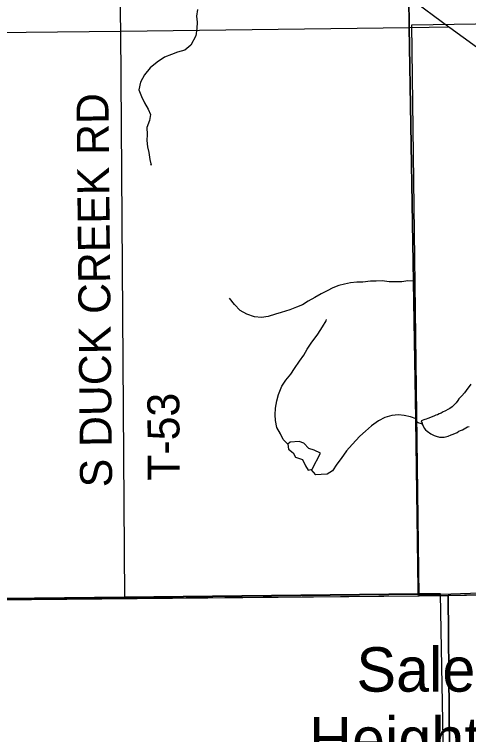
# Model space of a CAD drawing. Extents: x 0 to 34, y 0 to 22.
# Drawn here: x 2.754 to 3.561, y 16.976 to 18.256 of the extents above; entities that cross this region are included whole.
import ezdxf

# ---------------------------------------------------------------- set-up
doc = ezdxf.new("R2010")
doc.units = 0
for name, color, linetype in [('GM_X_County_Road', 7, 'Continuous'), ('GM_X_Minor_Lake', 7, 'Continuous'), ('GM_X_Minor_River', 7, 'Continuous'), ('GM_X_Rail_Line', 7, 'Continuous'), ('GM_X_Section', 7, 'Continuous'), ('GM_X_State_Route', 7, 'Continuous'), ('GM_X_Township', 7, 'Continuous'), ('GM_X_Township_Road', 7, 'Continuous'), ('GM_X_Township_Road_Text', 7, 'Continuous'), ('GM_X_Unincorporated_Text', 7, 'Continuous'), ('GM_X_US_Route', 7, 'Continuous'), ('SH_Cut_Line', 7, 'Continuous')]:
    doc.layers.add(name, color=color, linetype=linetype)

msp = doc.modelspace()

# ---------------------------------------------------------------- linework, layer by layer
at = {"layer": 'GM_X_County_Road'}
msp.add_lwpolyline([(2.1, 18.2179), (2.9425, 18.2267), (3.4555, 18.2333)], dxfattribs=at)
at = {"layer": 'GM_X_Minor_Lake'}
for points in [[(3.5646, 17.5993), (3.5564, 17.5878), (3.5534, 17.584), (3.5489, 17.5786), (3.5463, 17.5763)], [(3.5463, 17.5763), (3.5433, 17.5729), (3.5414, 17.5698), (3.5384, 17.566), (3.535, 17.5621), (3.5313, 17.5587), (3.5275, 17.5556), (3.5249, 17.5544), (3.5185, 17.5509), (3.5155, 17.5497), (3.5117, 17.5478), (3.5087, 17.5466), (3.5053, 17.5447), (3.5026, 17.5439), (3.4992, 17.5423), (3.4883, 17.538), (3.4856, 17.5372), (3.483, 17.5364), (3.4764, 17.5337)], [(3.4764, 17.5337), (3.4781, 17.5299), (3.4789, 17.5273), (3.482, 17.5212), (3.4843, 17.5182), (3.4874, 17.5156), (3.4939, 17.5107), (3.4996, 17.5077), (3.5031, 17.5066), (3.5092, 17.5052), (3.5118, 17.5048), (3.5175, 17.5049), (3.5243, 17.5069), (3.53, 17.5092), (3.5334, 17.5104), (3.5405, 17.5135), (3.5435, 17.5155), (3.5466, 17.517), (3.5496, 17.5182), (3.559, 17.5233), (3.5617, 17.5241)], [(3.2974, 17.4764), (3.2864, 17.482), (3.2769, 17.4846), (3.2681, 17.494), (3.2597, 17.4974), (3.2435, 17.4961), (3.2393, 17.4922), (3.2406, 17.4835), (3.249, 17.4768), (3.2532, 17.4696), (3.2653, 17.4651), (3.2711, 17.4538), (3.2754, 17.4462), (3.2825, 17.4482)], [(3.2825, 17.4482), (3.2974, 17.4764)]]:
    msp.add_lwpolyline(points, dxfattribs=at)
at = {"layer": 'GM_X_Minor_River'}
for points in [[(3.0789, 18.2654), (3.0771, 18.2536), (3.0784, 18.2426), (3.0777, 18.2312), (3.0759, 18.2183), (3.067, 18.2015), (3.0565, 18.1931), (3.0433, 18.1892), (3.0327, 18.1849), (3.0206, 18.1806), (3.0071, 18.1714), (2.9947, 18.1614), (2.985, 18.1488), (2.9779, 18.1358), (2.975, 18.1221), (2.9796, 18.1104), (2.9847, 18.0991), (2.9912, 18.0881), (2.9954, 18.0783), (2.9937, 18.0676), (2.9888, 18.0554), (2.9893, 18.0429), (2.9887, 18.0323), (2.9903, 18.0209), (2.9927, 18.011), (2.9943, 17.9985), (2.9967, 17.9883), (2.9963, 17.9894)], [(3.4635, 17.782), (3.4528, 17.7826), (3.4419, 17.781), (3.4309, 17.7809), (3.4195, 17.7812), (3.4074, 17.7826), (3.3964, 17.7825), (3.3862, 17.782), (3.3726, 17.7804), (3.3624, 17.7803), (3.3507, 17.7795), (3.3401, 17.7771), (3.3299, 17.7747), (3.3193, 17.7701), (3.3095, 17.7651), (3.2986, 17.7597), (3.2877, 17.7531), (3.2756, 17.7466), (3.2655, 17.74), (3.2549, 17.7361), (3.2428, 17.7315), (3.2277, 17.7268), (3.2175, 17.7233), (3.2047, 17.7194), (3.1926, 17.7174), (3.1801, 17.7188), (3.1668, 17.7236), (3.1546, 17.7299), (3.1447, 17.7405), (3.1359, 17.7518)], [(3.2393, 17.4922), (3.2313, 17.5009), (3.2263, 17.5111), (3.2201, 17.5221), (3.2178, 17.5346), (3.2169, 17.5448), (3.2176, 17.5562), (3.2197, 17.5695), (3.223, 17.5809), (3.2289, 17.5954), (3.236, 17.6061), (3.245, 17.6168), (3.2514, 17.6267), (3.2603, 17.6401), (3.2678, 17.6508), (3.2741, 17.6615), (3.2812, 17.6718), (3.2928, 17.6882), (3.301, 17.7012), (3.3074, 17.7115), (3.3085, 17.7142)], [(3.4673, 17.5375), (3.4577, 17.5412), (3.4463, 17.5434), (3.4361, 17.5444), (3.4244, 17.5432), (3.4119, 17.54), (3.4006, 17.5342), (3.3882, 17.525), (3.3777, 17.5154), (3.3672, 17.5066), (3.3537, 17.4921), (3.3439, 17.4806), (3.3342, 17.4669), (3.3264, 17.4569), (3.3189, 17.4451), (3.3091, 17.4393), (3.2989, 17.4388), (3.2891, 17.438), (3.2808, 17.4477)], [(3.4789, 17.5275), (3.477, 17.5284), (3.4713, 17.5306), (3.4674, 17.5327)]]:
    msp.add_lwpolyline(points, dxfattribs=at)
at = {"layer": 'GM_X_Rail_Line'}
for points in [[(2.5218, 17.2155), (2.9494, 17.2203), (3.4711, 17.2262), (3.471, 17.2341), (3.467, 17.5367), (3.4553, 18.2338), (3.4545, 18.2877)], [(5.1569, 17.2563), (4.8882, 17.2522), (4.6131, 17.2468), (3.47, 17.2222), (2.5105, 17.2141), (2.1, 17.2106)]]:
    msp.add_lwpolyline(points, dxfattribs=at)
msp.add_lwpolyline([(2.1, 17.2107), (2.1, 14.1), (5.5619, 14.1), (5.5608, 14.205), (5.5615, 14.2414), (5.5595, 14.6439), (5.5583, 14.9347), (5.5581, 14.9676), (5.5588, 15.1747), (5.5579, 15.2049), (4.0847, 15.1965), (3.5411, 15.1931), (3.5298, 15.9318), (3.5269, 16.3549), (3.511, 17.2267), (3.4711, 17.2262), (2.9494, 17.2203), (2.5218, 17.2155)], close=True, dxfattribs=at)
at = {"layer": 'GM_X_Section'}
for points in [[(4.5147, 18.2545), (4.5299, 17.2417), (3.5245, 17.2236), (3.4729, 17.2231), (3.4598, 18.2381)], [(4.5299, 17.2417), (4.5462, 16.1923), (3.5333, 16.1865), (3.5245, 17.2236)], [(3.5245, 17.2236), (3.5333, 16.1865), (2.5362, 16.1651), (2.5329, 17.2138), (3.4729, 17.2231)]]:
    msp.add_lwpolyline(points, close=True, dxfattribs=at)
at = {"layer": 'GM_X_State_Route'}
for p, q in [((3.4547, 18.2871), (3.5257, 18.2344)), ((2.522, 17.215), (2.9496, 17.2198)), ((2.9496, 17.2198), (3.4713, 17.2256))]:
    msp.add_line(p, q, dxfattribs=at)
for points in [[(3.5257, 18.2344), (3.5273, 18.2332), (3.9345, 17.9383), (4.1204, 17.8241), (4.1591, 17.796)], [(3.4713, 17.2256), (3.5112, 17.2261), (3.7398, 17.2335)]]:
    msp.add_lwpolyline(points, dxfattribs=at)
at = {"layer": 'GM_X_Township'}
msp.add_lwpolyline([(3.5411, 15.1931), (3.5298, 15.9318), (3.5269, 16.3549), (3.511, 17.2267), (3.4711, 17.2262), (3.471, 17.2341), (3.467, 17.5367), (3.4553, 18.2338), (3.4545, 18.2877)], dxfattribs=at)
at = {"layer": 'GM_X_Township_Road'}
for p, q in [((2.9425, 18.2267), (2.9341, 18.6634)), ((3.4555, 18.2333), (3.5257, 18.2344)), ((2.9496, 17.2198), (2.9425, 18.2267))]:
    msp.add_line(p, q, dxfattribs=at)
msp.add_lwpolyline([(3.4713, 17.2256), (3.4712, 17.2336), (3.4672, 17.5362)], dxfattribs=at)
at = {"layer": 'GM_X_US_Route'}
for p, q in [((2.522, 17.215), (2.9496, 17.2198)), ((2.9496, 17.2198), (3.4713, 17.2256))]:
    msp.add_line(p, q, dxfattribs=at)
msp.add_lwpolyline([(3.4713, 17.2256), (3.5112, 17.2261), (3.7398, 17.2335)], dxfattribs=at)
at = {"layer": 'SH_Cut_Line'}
for points in [[(2.5218, 17.2155), (2.9494, 17.2203), (3.4711, 17.2262), (3.471, 17.2341), (3.467, 17.5367), (3.4553, 18.2338), (3.4545, 18.2877)], [(3.4545, 18.2877), (3.4553, 18.2338), (3.467, 17.5367), (3.471, 17.2341), (3.4711, 17.2262), (2.9494, 17.2203), (2.5218, 17.2155)]]:
    msp.add_lwpolyline(points, dxfattribs=at)

# ---------------------------------------------------------------- texts
at = {"layer": 'GM_X_Township_Road_Text'}
for s, height, rotation, p in [('S DUCK CREEK RD', 0.056818, 90.5464, (2.9273, 17.416)), ('T-53', 0.05682, 90.3535, (3.0475, 17.4277))]:
    msp.add_text(s, height=height, rotation=rotation, dxfattribs=at).set_placement(p)
at = {"layer": 'GM_X_Unincorporated_Text'}
for s, p in [('Salem', (3.3614, 17.0525)), ('Heights', (3.2772, 16.9283))]:
    msp.add_text(s, height=0.07898, rotation=0, dxfattribs=at).set_placement(p)

doc.saveas('drawing.dxf')
